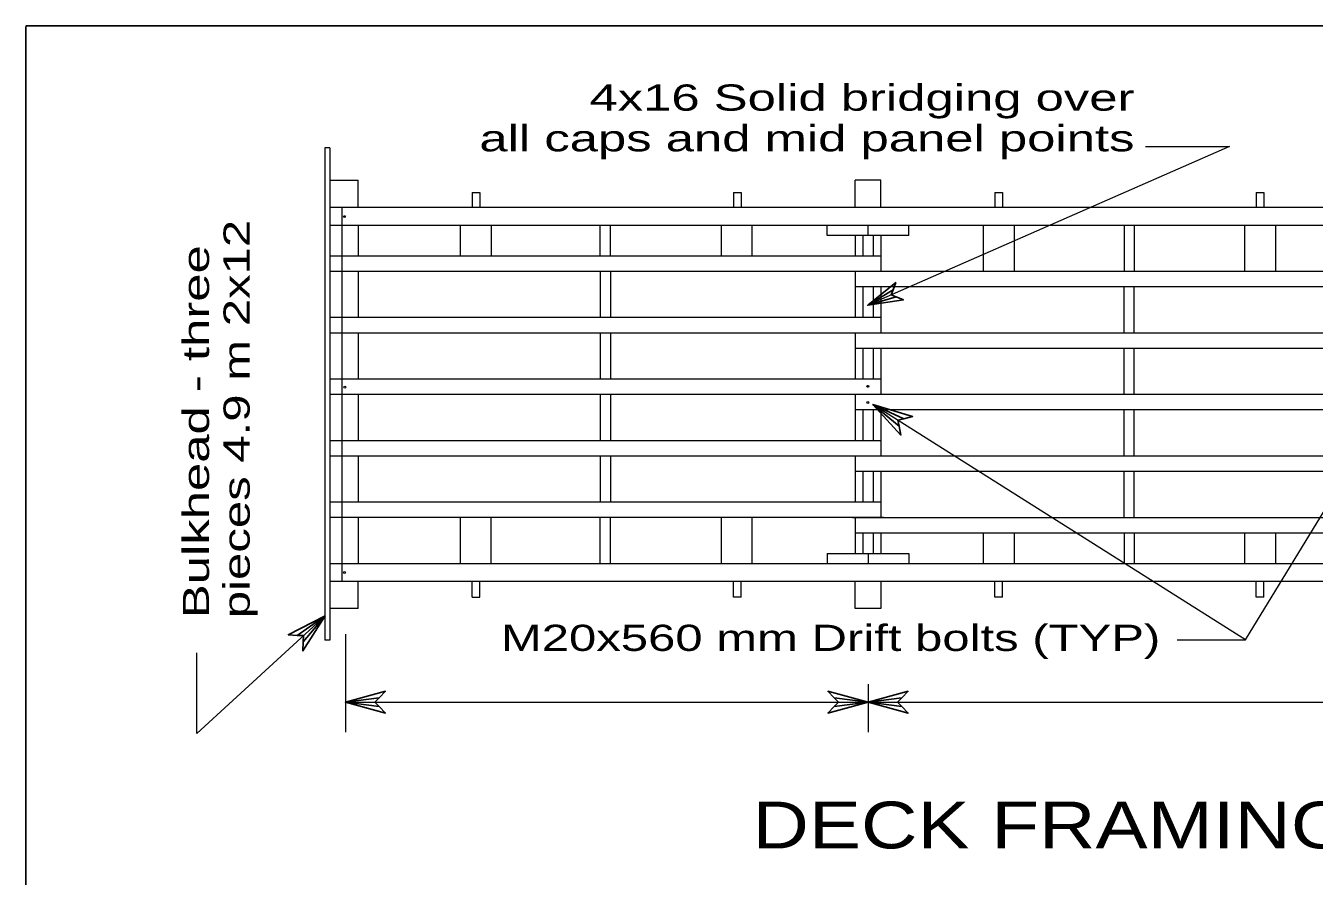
# Model space of a CAD drawing. Extents: x 13426 to 15509, y -9298 to -5111.
# Drawn here: x 15181.1 to 15245.4, y -5422.2 to -5379.8 of the extents above; entities that cross this region are included whole.
import ezdxf
from ezdxf.enums import TextEntityAlignment as Align

# ---------------------------------------------------------------- set-up
doc = ezdxf.new("R2010")
doc.units = 0
doc.header["$LTSCALE"] = 0.52
for name, color, linetype, lineweight in [('1', 7, 'Continuous', 13), ('15', 7, 'Continuous', 13), ('16', 7, 'Continuous', 25), ('2', 7, 'Continuous', 25), ('20', 7, 'Continuous', 13), ('3', 7, 'Continuous', 25), ('30', 7, 'Continuous', 25), ('4', 7, 'Continuous', 13), ('5', 7, 'Continuous', 25), ('6', 7, 'Continuous', 13)]:
    doc.layers.add(name, color=color, linetype=linetype, lineweight=lineweight)
doc.layers.add('19', color=7, linetype='Continuous')

msp = doc.modelspace()

# ---------------------------------------------------------------- linework, layer by layer
at = {"layer": '1'}
for p, q in [((15196.297, -5387.513), (15197.703, -5387.513)), ((15197.703, -5388.864), (15197.703, -5387.513)), ((15223.782, -5387.513), (15222.504, -5387.513)), ((15222.504, -5388.864), (15222.504, -5387.513)), ((15223.782, -5388.864), (15223.782, -5387.513)), ((15203.392, -5388.119), (15203.776, -5388.119)), ((15203.392, -5388.119), (15203.392, -5388.864)), ((15203.776, -5388.119), (15203.776, -5388.864)), ((15216.431, -5388.119), (15216.815, -5388.119)), ((15216.431, -5388.119), (15216.431, -5388.864)), ((15216.815, -5388.119), (15216.815, -5388.864)), ((15229.471, -5388.119), (15229.855, -5388.119)), ((15229.471, -5388.119), (15229.471, -5388.864)), ((15229.855, -5388.119), (15229.855, -5388.864)), ((15242.511, -5388.119), (15242.894, -5388.119)), ((15242.511, -5388.119), (15242.511, -5388.864)), ((15242.894, -5388.119), (15242.894, -5388.864)), ((15314.42, -5388.864), (15196.297, -5388.864)), ((15314.42, -5389.758), (15196.297, -5389.758)), ((15197.703, -5389.758), (15197.703, -5391.293)), ((15222.504, -5390.272), (15222.504, -5391.293)), ((15223.782, -5390.272), (15223.782, -5392.06)), ((15197.703, -5392.06), (15197.703, -5394.361)), ((15222.504, -5392.06), (15222.504, -5394.361)), ((15223.782, -5392.827), (15223.782, -5395.128)), ((15197.703, -5395.128), (15197.703, -5397.429)), ((15222.504, -5395.128), (15222.504, -5397.429)), ((15223.782, -5395.895), (15223.782, -5398.196)), ((15197.703, -5398.196), (15197.703, -5400.497)), ((15222.504, -5398.196), (15222.504, -5400.497)), ((15223.782, -5398.963), (15223.782, -5401.264)), ((15197.703, -5401.264), (15197.703, -5403.565)), ((15222.504, -5401.264), (15222.504, -5403.565)), ((15223.782, -5402.031), (15223.782, -5404.332)), ((15197.703, -5404.332), (15197.703, -5406.632)), ((15222.504, -5404.332), (15222.504, -5406.12)), ((15223.782, -5405.099), (15223.782, -5406.12)), ((15314.42, -5406.632), (15196.297, -5406.632)), ((15314.42, -5407.516), (15196.297, -5407.516)), ((15197.703, -5408.868), (15197.703, -5407.526)), ((15203.392, -5408.301), (15203.392, -5407.526)), ((15203.776, -5408.301), (15203.776, -5407.526)), ((15216.431, -5408.301), (15216.431, -5407.526)), ((15216.815, -5408.301), (15216.815, -5407.526)), ((15222.504, -5408.868), (15222.504, -5407.517)), ((15223.782, -5407.517), (15223.782, -5408.868)), ((15229.471, -5408.301), (15229.471, -5407.526)), ((15229.855, -5408.301), (15229.855, -5407.526)), ((15242.511, -5408.301), (15242.511, -5407.526)), ((15242.894, -5408.301), (15242.894, -5407.526)), ((15203.392, -5408.301), (15203.776, -5408.301)), ((15216.815, -5408.301), (15216.431, -5408.301)), ((15229.855, -5408.301), (15229.471, -5408.301)), ((15242.894, -5408.301), (15242.511, -5408.301)), ((15197.703, -5408.868), (15196.297, -5408.868)), ((15223.782, -5408.868), (15222.504, -5408.868))]:
    msp.add_line(p, q, dxfattribs=at)
at = {"layer": '15'}
for p, q in [((15241.981, -5410.423), (15249.092, -5398.762)), ((15197.064, -5410.145), (15197.064, -5415.033)), ((15223.143, -5412.636), (15223.143, -5415.034)), ((15197.064, -5413.535), (15223.143, -5413.535)), ((15223.143, -5413.535), (15249.222, -5413.535))]:
    msp.add_line(p, q, dxfattribs=at)
for points in [[(15236.982, -5385.829), (15241.183, -5385.829), (15223.132, -5393.739)], [(15238.573, -5410.423), (15241.981, -5410.423), (15223.388, -5398.685)], [(15196.055, -5409.225), (15189.66, -5415.088), (15189.66, -5411.07)]]:
    msp.add_lwpolyline(points, dxfattribs=at)
at = {"layer": '16'}
for points in [[(15224.55, -5393.327), (15224.911, -5393.476), (15223.132, -5393.739), (15224.531, -5392.609), (15224.397, -5392.976), (15223.132, -5393.739), (15224.55, -5393.327), (15224.298, -5393.228), (15224.397, -5392.976)], [(15224.697, -5399.772), (15224.788, -5400.213), (15223.388, -5398.685), (15225.37, -5399.291), (15224.933, -5399.399), (15223.388, -5398.685), (15224.697, -5399.772), (15224.628, -5399.468), (15224.933, -5399.399)], [(15194.662, -5410.203), (15194.213, -5410.174), (15196.055, -5409.225), (15194.95, -5410.977), (15194.96, -5410.527), (15196.055, -5409.225), (15194.662, -5410.203), (15194.974, -5410.216), (15194.96, -5410.527)], [(15198.751, -5413.755), (15199.063, -5414.08), (15197.064, -5413.535), (15199.063, -5412.99), (15198.751, -5413.314), (15197.064, -5413.535), (15198.751, -5413.755), (15198.531, -5413.535), (15198.751, -5413.314)], [(15221.456, -5413.314), (15221.145, -5412.99), (15223.143, -5413.535), (15221.145, -5414.08), (15221.456, -5413.755), (15223.143, -5413.535), (15221.456, -5413.314), (15221.677, -5413.535), (15221.456, -5413.755)], [(15224.83, -5413.756), (15225.142, -5414.081), (15223.143, -5413.535), (15225.142, -5412.99), (15224.83, -5413.315), (15223.143, -5413.535), (15224.83, -5413.756), (15224.609, -5413.535), (15224.83, -5413.315)]]:
    msp.add_lwpolyline(points, dxfattribs=at)
at = {"layer": '2', "lineweight": 13}
for p, q in [((15196.297, -5385.898), (15196.041, -5385.898)), ((15196.041, -5385.898), (15196.041, -5410.443)), ((15196.297, -5385.898), (15196.297, -5410.443)), ((15223.782, -5391.293), (15196.297, -5391.293)), ((15224.81, -5392.06), (15196.297, -5392.06)), ((15276.968, -5392.06), (15222.376, -5392.06)), ((15249.861, -5392.827), (15222.504, -5392.827)), ((15225.558, -5392.827), (15222.504, -5392.827)), ((15223.782, -5394.361), (15196.297, -5394.361)), ((15223.91, -5395.128), (15196.297, -5395.128)), ((15279.679, -5395.128), (15222.376, -5395.128)), ((15249.861, -5395.896), (15222.504, -5395.896)), ((15223.782, -5397.429), (15196.297, -5397.429)), ((15223.91, -5398.196), (15196.297, -5398.196)), ((15281.329, -5398.196), (15222.376, -5398.196)), ((15249.861, -5398.963), (15222.504, -5398.963)), ((15223.782, -5400.497), (15196.297, -5400.497)), ((15223.91, -5401.264), (15196.297, -5401.264)), ((15282.747, -5401.264), (15222.376, -5401.264)), ((15249.861, -5402.031), (15222.504, -5402.031)), ((15223.782, -5403.565), (15196.297, -5403.565)), ((15223.91, -5404.332), (15196.297, -5404.332)), ((15284.148, -5404.333), (15222.376, -5404.333)), ((15249.861, -5405.1), (15222.504, -5405.1)), ((15196.297, -5410.443), (15196.041, -5410.443))]:
    msp.add_line(p, q, dxfattribs=at)
at = {"layer": '3', "lineweight": 13}
for p, q in [((15223.143, -5390.272), (15223.143, -5389.791)), ((15225.188, -5390.272), (15225.188, -5389.761)), ((15225.188, -5390.272), (15223.143, -5390.272)), ((15221.098, -5406.12), (15223.143, -5406.12)), ((15221.098, -5406.12), (15221.098, -5406.631)), ((15223.143, -5406.12), (15225.188, -5406.12)), ((15223.143, -5406.12), (15223.143, -5406.631)), ((15225.188, -5406.12), (15225.188, -5406.631))]:
    msp.add_line(p, q, dxfattribs=at)
msp.add_lwpolyline([(15223.143, -5390.272), (15221.098, -5390.272), (15221.098, -5389.761)], dxfattribs=at)
at = {"layer": '30'}
for p, q in [((15509.151, -5379.809), (15181.119, -5379.809)), ((15181.119, -5379.846), (15181.119, -5592.065))]:
    msp.add_line(p, q, dxfattribs=at)
at = {"layer": '4'}
for p, q in [((15196.888, -5388.864), (15196.888, -5407.526)), ((15209.784, -5391.293), (15209.784, -5389.759)), ((15210.295, -5391.293), (15210.295, -5389.759)), ((15235.916, -5389.759), (15235.916, -5392.058)), ((15236.427, -5389.759), (15236.427, -5392.058)), ((15222.888, -5390.272), (15222.888, -5391.293)), ((15223.399, -5390.272), (15223.399, -5391.293)), ((15209.784, -5392.06), (15209.784, -5394.361)), ((15210.295, -5392.06), (15210.295, -5394.361)), ((15222.888, -5392.827), (15222.888, -5394.361)), ((15223.399, -5392.827), (15223.399, -5394.361)), ((15235.916, -5395.128), (15235.916, -5392.827)), ((15236.427, -5395.128), (15236.427, -5392.827)), ((15209.784, -5395.128), (15209.784, -5397.429)), ((15210.295, -5395.128), (15210.295, -5397.429)), ((15222.888, -5395.895), (15222.888, -5397.429)), ((15223.399, -5395.895), (15223.399, -5397.429)), ((15235.916, -5398.196), (15235.916, -5395.896)), ((15236.427, -5398.196), (15236.427, -5395.896)), ((15209.784, -5398.196), (15209.784, -5400.497)), ((15210.295, -5398.196), (15210.295, -5400.497)), ((15222.888, -5398.963), (15222.888, -5400.497)), ((15223.399, -5398.963), (15223.399, -5400.497)), ((15235.916, -5401.264), (15235.916, -5398.963)), ((15236.427, -5401.264), (15236.427, -5398.963)), ((15209.784, -5401.264), (15209.784, -5403.565)), ((15210.295, -5401.264), (15210.295, -5403.565)), ((15222.888, -5402.031), (15222.888, -5403.565)), ((15223.399, -5402.031), (15223.399, -5403.565)), ((15235.916, -5404.333), (15235.916, -5402.031)), ((15236.427, -5404.333), (15236.427, -5402.031)), ((15209.784, -5406.632), (15209.784, -5404.332)), ((15210.295, -5406.632), (15210.295, -5404.332)), ((15222.888, -5405.099), (15222.888, -5406.12)), ((15223.399, -5405.099), (15223.399, -5406.12)), ((15235.916, -5405.1), (15235.916, -5406.632)), ((15236.427, -5405.1), (15236.427, -5406.632))]:
    msp.add_line(p, q, dxfattribs=at)
at = {"layer": '5', "lineweight": 13}
for p, q in [((15202.812, -5391.294), (15202.812, -5389.759)), ((15204.352, -5391.294), (15204.352, -5389.759)), ((15215.828, -5391.293), (15215.828, -5389.759)), ((15217.367, -5391.293), (15217.367, -5389.759)), ((15228.889, -5389.759), (15228.889, -5392.06)), ((15230.428, -5389.759), (15230.428, -5392.06)), ((15241.934, -5389.761), (15241.934, -5392.06)), ((15243.474, -5389.761), (15243.474, -5392.06)), ((15202.806, -5406.632), (15202.806, -5404.332)), ((15204.346, -5406.632), (15204.346, -5404.332)), ((15215.831, -5406.631), (15215.831, -5404.332)), ((15217.371, -5406.631), (15217.371, -5404.332)), ((15228.89, -5405.1), (15228.89, -5406.63)), ((15230.43, -5405.1), (15230.43, -5406.63)), ((15241.93, -5405.1), (15241.93, -5406.632)), ((15243.47, -5405.1), (15243.47, -5406.632))]:
    msp.add_line(p, q, dxfattribs=at)
at = {"layer": '6'}
for centre in [(15197.0155, -5389.3247), (15197.0346, -5397.8203), (15223.1301, -5397.785), (15223.136, -5398.5862), (15197.0236, -5407.0626)]:
    msp.add_circle(centre, 0.0479, dxfattribs=at)

# ---------------------------------------------------------------- texts
at = {"layer": '19'}
for s, width, p in [('pieces 4.9 m 2x12', 1.4, (15192.291, -5409.344)), ('Bulkhead - three', 1.45, (15190.263, -5409.344))]:
    msp.add_text(s, height=1.307, rotation=90, dxfattribs=dict(at, width=width)).set_placement(p)
at = {"layer": '19', "width": 1.4}
msp.add_text('M20x560 mm Drift bolts (TYP)', height=1.307, dxfattribs=at).set_placement((15237.727, -5410.978), align=Align.RIGHT)
at = {"layer": '20', "width": 1.45}
for s, p in [('4x16 Solid bridging over', (15236.436, -5384.041)), ('all caps and mid panel points', (15236.437, -5386.069))]:
    msp.add_text(s, height=1.307, dxfattribs=at).set_placement(p, align=Align.RIGHT)
at = {"layer": '20', "width": 1.25}
msp.add_text('DECK FRAMING PLAN - SINGLE LANE', height=2.333, dxfattribs=at).set_placement((15252.481, -5420.823), align=Align.CENTER)

doc.saveas('drawing.dxf')
